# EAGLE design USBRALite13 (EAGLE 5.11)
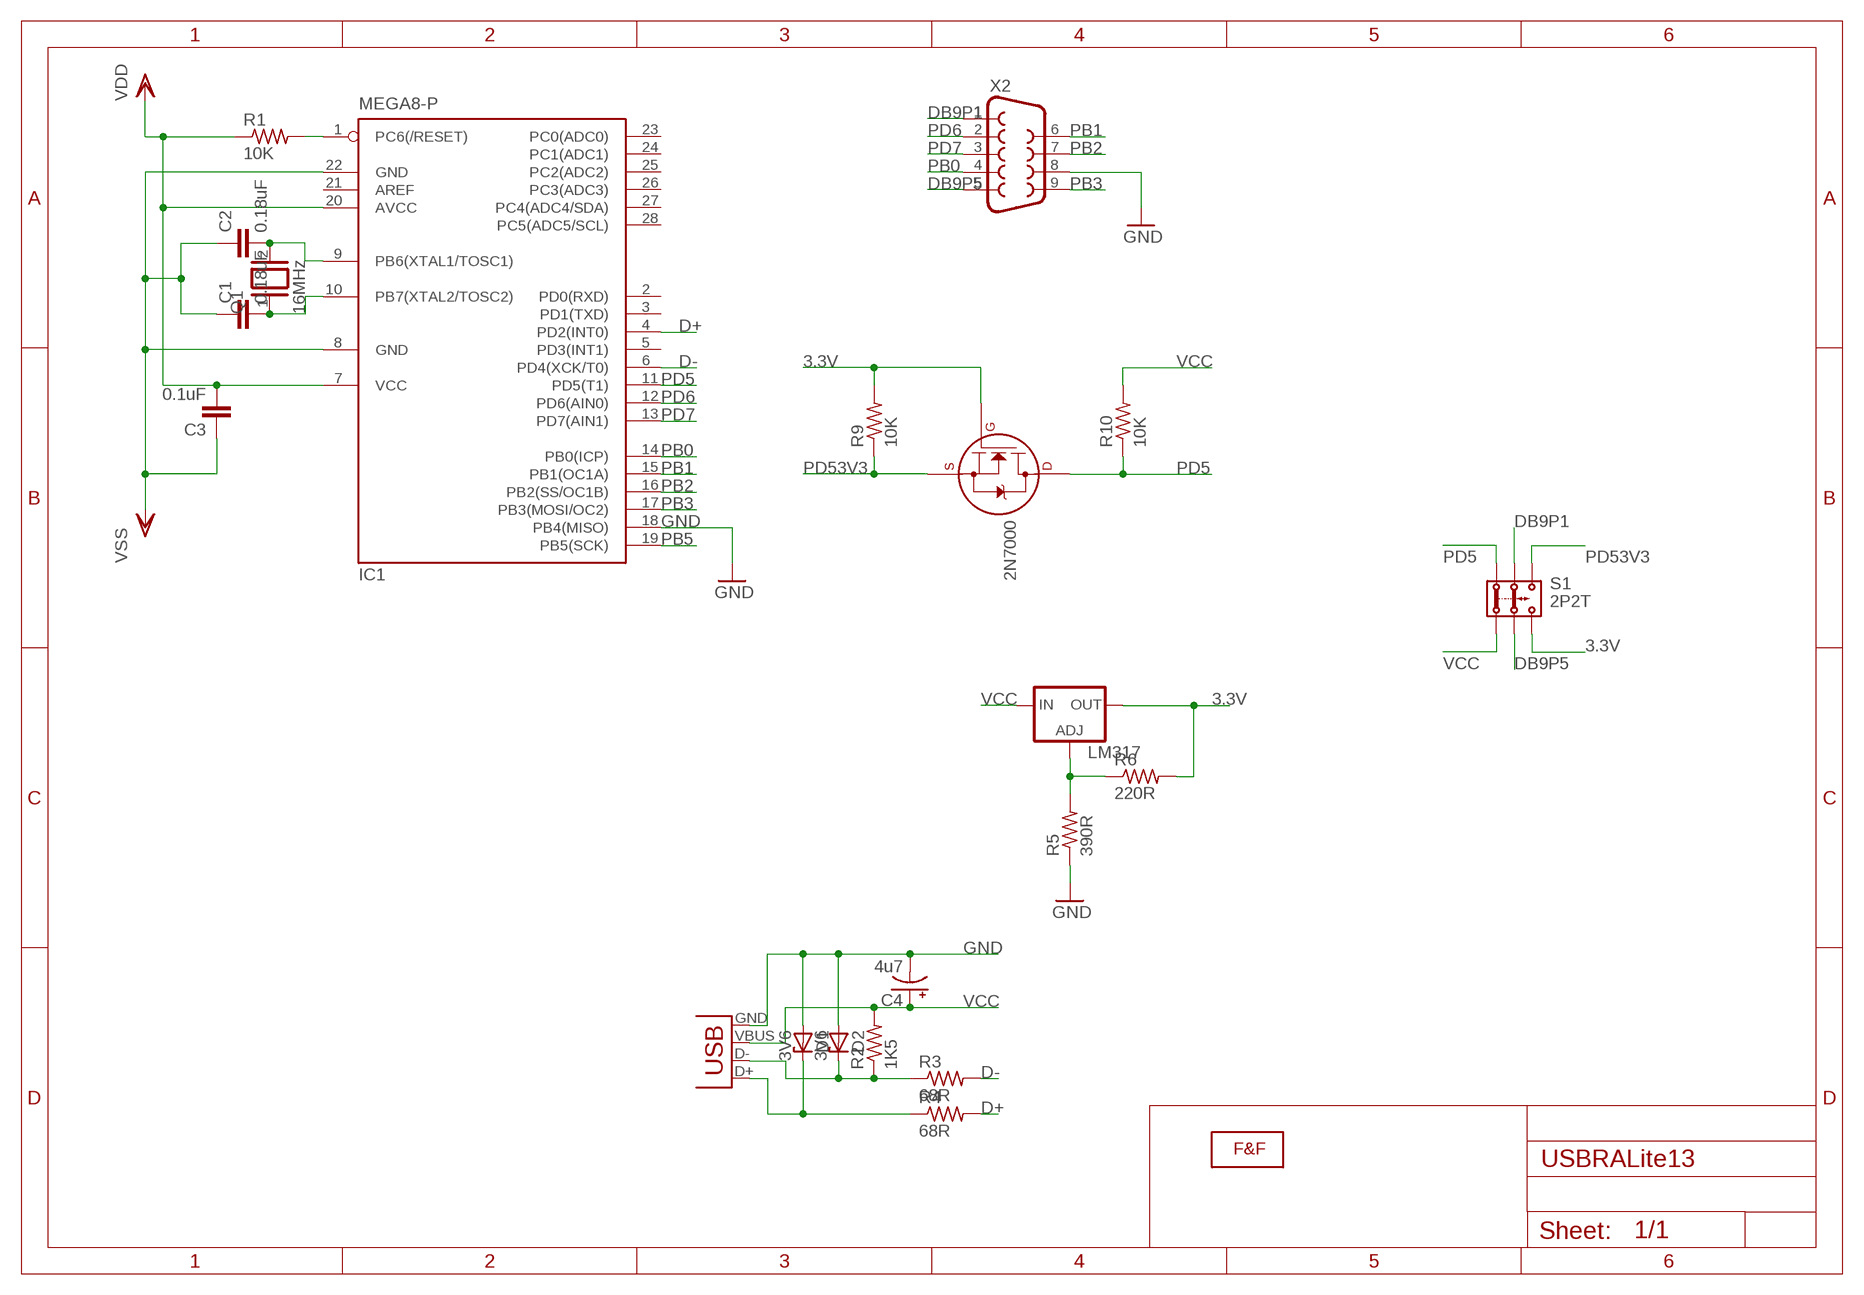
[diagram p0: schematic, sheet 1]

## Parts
2N7000  2N7000_TO92  [TO-92]
C1  0.18uF  C-EU050-024X044  [C050-024X044]
C2  0.18uF  C-EU050-024X044  [C050-024X044]
C3  0.1uF  C-EU050-024X044  [C050-024X044]
C4  4u7  CPOL-USE2.5-6  [E2,5-6]
D1  3V6  ZENER-DIODEZD-5  [ZDIO-5]
D2  3V6  ZENER-DIODEZD-5  [ZDIO-5]
IC1  MEGA8-P  [DIL28-3]
LM317  LM317TS  [317TS]
Q1  16MHz  XTAL/S  [QS]
R1  10K  R-US_0207/10  [0207/10]
R2  1K5  R-US_0207/10  [0207/10]
R3  68R  R-US_0207/10  [0207/10]
R4  68R  R-US_0207/10  [0207/10]
R5  390R  R-US_0207/10  [0207/10]
R6  220R  R-US_0207/10  [0207/10]
R9  10K  R-US_0207/10  [0207/10]
R10  10K  R-US_0207/10  [0207/10]
S1  2P2T  [2P2T]
U$1  LOGOLOGO_WITHOUT_SMOKE_SMALL  [LOGO2_SMALL]
X1  USBPTH  [USB-B-PTH]
X2  DB9MALE  [DB9_MALE]

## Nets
3.3V: 2N7000.2(G) LM317.2(OUT) R6.2 R9.2 S1.3.2
D+: IC1.4(PD2(INT0)) R4.2
D-: IC1.6(PD4(XCK/T0)) R3.2
DB9P1: S1.2.1 X2.1
DB9P5: S1.2.2 X2.5
GND: C1.1 C2.1 C3.1 C4.- D1.A D2.A IC1.8(GND) IC1.18(PB4(MISO)) IC1.22(GND) R5.1 X1.GND X2.8 ; supply symbol labelled VSS
N$1: IC1.1(PC6(/RESET)) R1.2
N$2: C2.2 IC1.9(PB6(XTAL1/TOSC1)) Q1.2
N$3: C1.2 IC1.10(PB7(XTAL2/TOSC2)) Q1.1
N$5: LM317.1(ADJ) R5.2 R6.1
N$8: D1.C R4.1 X1.D+
N$9: D2.C R2.1 R3.1 X1.D-
PB0: IC1.14(PB0(ICP)) X2.4
PB1: IC1.15(PB1(OC1A)) X2.6
PB2: IC1.16(PB2(SS/OC1B)) X2.7
PB3: IC1.17(PB3(MOSI/OC2)) X2.9
PB5: IC1.19(PB5(SCK))
PD5: 2N7000.3(D) IC1.11(PD5(T1)) R10.1 S1.1.1
PD6: IC1.12(PD6(AIN0)) X2.2
PD7: IC1.13(PD7(AIN1)) X2.3
PD53V3: 2N7000.1(S) R9.1 S1.3.1
VCC: C3.2 C4.+ IC1.7(VCC) IC1.20(AVCC) LM317.3(IN) R1.1 R2.2 R10.2 S1.1.2 X1.VBUS ; supply symbol labelled VDD
Unconnected: IC1.2(PD0(RXD)) IC1.3(PD1(TXD)) IC1.5(PD3(INT1)) IC1.21(AREF) IC1.23(PC0(ADC0)) IC1.24(PC1(ADC1)) IC1.25(PC2(ADC2)) IC1.26(PC3(ADC3)) IC1.27(PC4(ADC4/SDA)) IC1.28(PC5(ADC5/SCL))

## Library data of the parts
2N7000 = transistors:2N700*: 2N7000, 2N7002, NDS7002A N-channel enhancement mode MOSFET
C1-C3 = rcl:C-EU: CAPACITOR, European symbol
C4 = adafruit:CPOL-US: POLARIZED CAPACITOR, American symbol
D1 D2 = diode:ZENER-DIODE: Z-Diode
IC1 = atmel:MEGA8-P: MICROCONTROLLER 8 Kbytes FLASH, 1 kbytes SRAM, 512 bytes EEPROM, USART, 4-channel 10 bit ADC, 2-channel 8 bit ADC Pin compatible with Atmega48, ATMega88, ATMega168 Source: avr.lbr; OC_FARNELL: unknown; OC_NEWARK: unknown
LM317 = v-reg:LM317TS: VOLTAGE REGULATOR
Q1 = special:XTAL/S: CRYSTAL
R1-R6 R9 R10 = adafruit:R-US_: RESISTOR, American symbol
S1 = Itead_BP_110825:2P2T: BAS011
U$1 = F&F:LOGO: Faísca e Fumaça Logo
X1 = SparkFun:USB: USB Connectors USB-B-PTH is fully proven SKU : PRT-00139 USB-miniB is fully proven SKU : PRT-00587 USB-A-PCB is untested. USB-A-H is throughly reviewed, but untested. Spark Fun Electronics SKU : PRT-00437 USB-B-SMT is throughly reviewed, but untested. Needs silkscreen touching up. USB-A-S has not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
X2 = SparkFun:DB9: DB9 Connector Standard DB9 (D-Sub 9) serial connector. Can be used for CAN bus as well as RS485 and RS232. Footprint production proven. Spark Fun Electronics SKU : PRT-00429

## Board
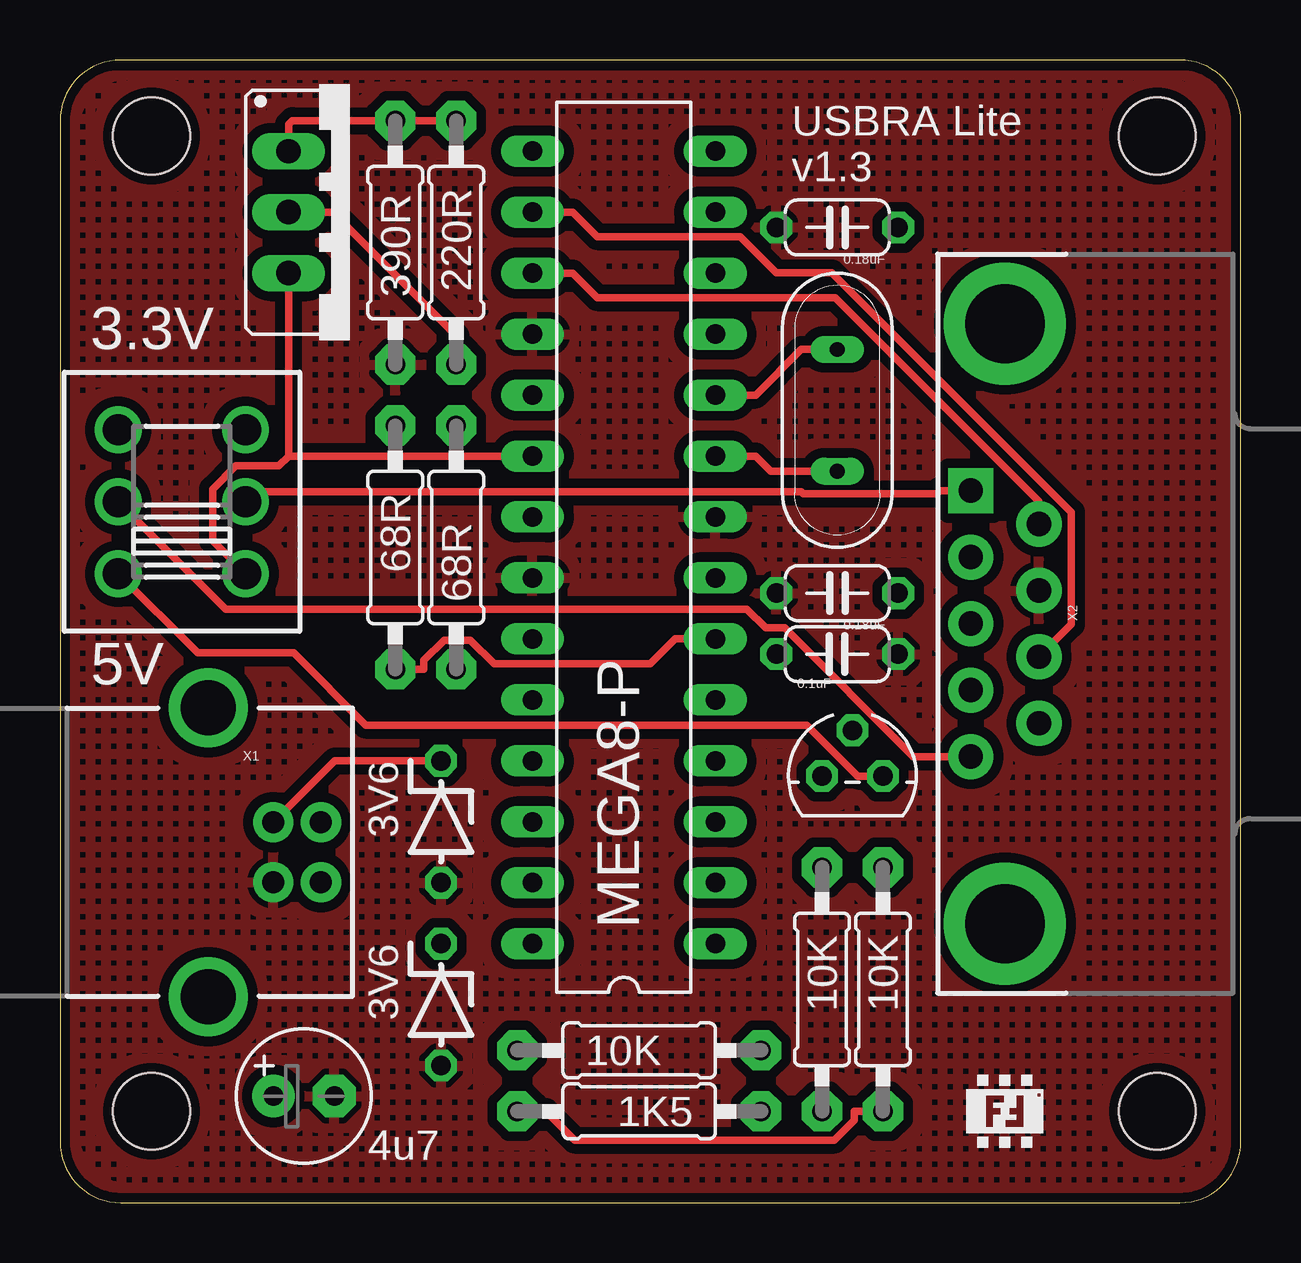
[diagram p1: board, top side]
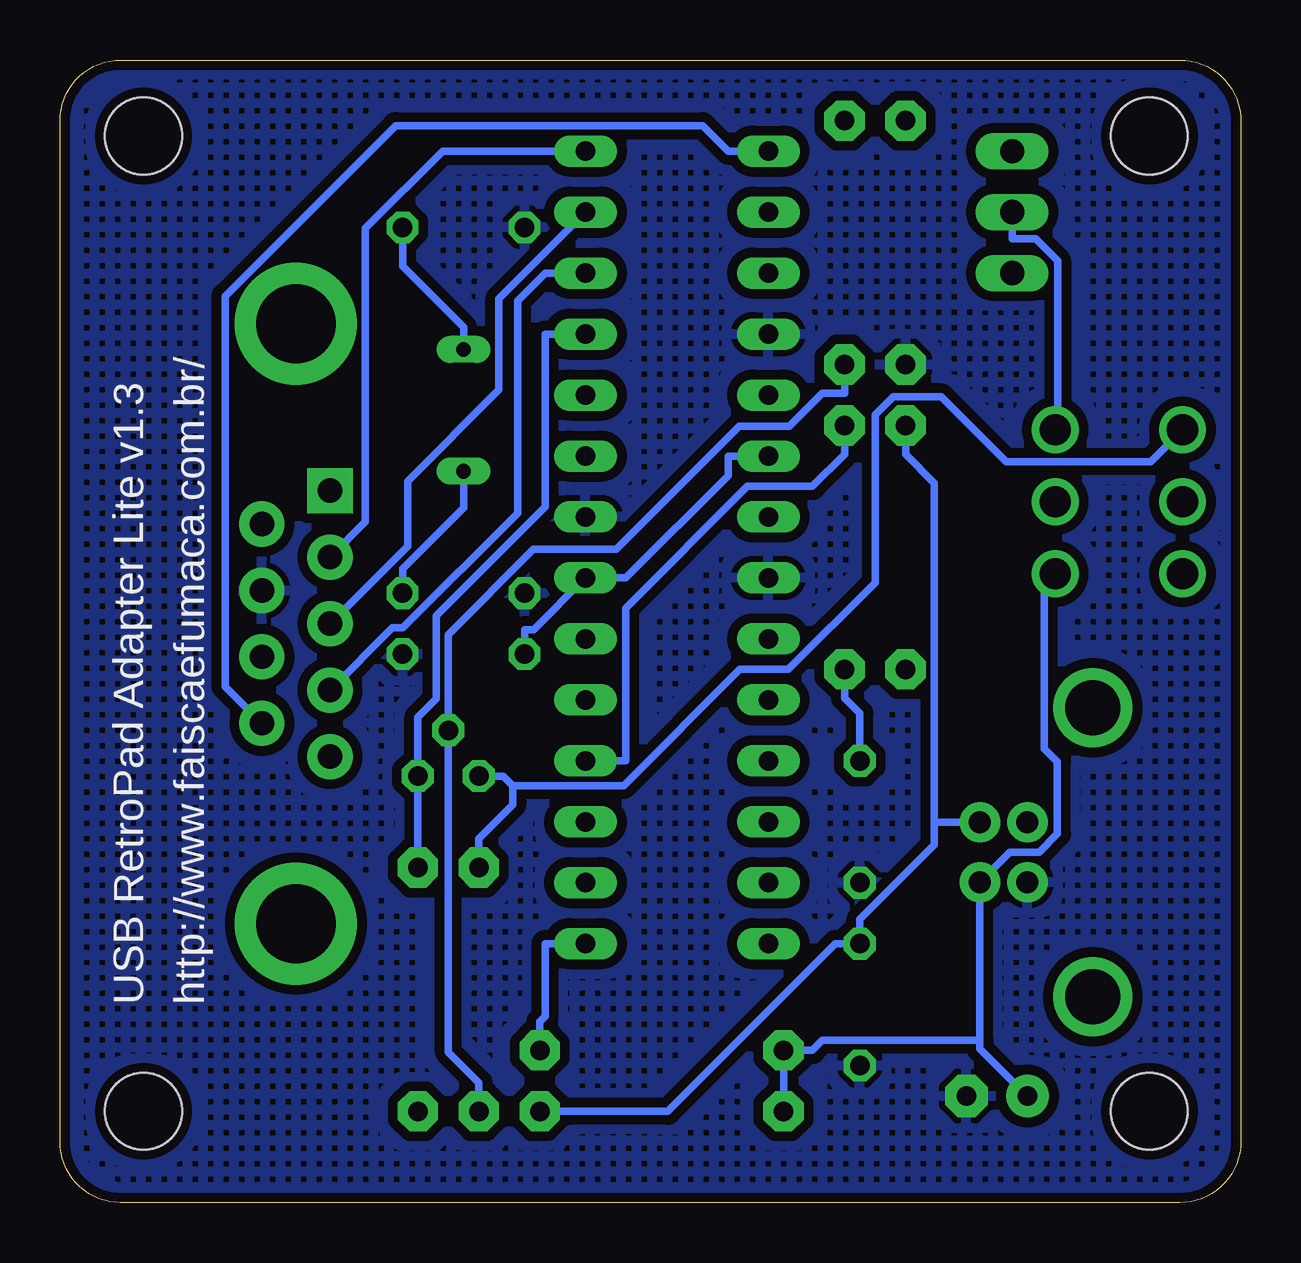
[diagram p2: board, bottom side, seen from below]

Size 49.2 x 47.62 mm. Coordinates in mm from the lower left corner, seen from the top.
Outline: 49.2,45.08 arc90 46.66,47.62 2.54,47.62 arc90 0,45.08 0,2.54 arc90 2.54,0 46.66,0 arc90 49.2,2.54 49.2,45.08
Copper layers (1*16): Top 0.035mm / dielectric 1.5mm / Bottom 0.035mm
Design rules "ITead_rule": minimum track width 6mil, minimum drill 12mil, track to track 6mil, track to pad 6mil, pad to pad 6mil, via to via 6mil, smd to smd 0mil, copper to edge 10mil, drill to drill 10mil, minimum pad ring 10mil, minimum via ring 6mil, stop-mask expansion 2mil, vias tented up to drill 100mil, thermal gap 10mil
Holes 3.2 mm at 3.81,44.45 3.81,3.81 45.72,44.45 45.72,3.81

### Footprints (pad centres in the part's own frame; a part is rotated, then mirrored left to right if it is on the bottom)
TO-92 = drill 0.813 octagon: 1 -1.27,0; 2 0,1.905; 3 1.27,0
C050-024X044 = drill 0.813 octagon: 1 -2.54,0; 2 2.54,0
E2,5-6 = drill 0.813 pad 1.778 round: + -1.27,0 | drill 0.813 pad 1.778 octagon: - 1.27,0
ZDIO-5 = drill 0.813 octagon: A 2.54,0; C -2.54,0
DIL28-3 = drill 0.813 long: 1 -16.51,-3.81; 2 -13.97,-3.81; 3 -11.43,-3.81; 4 -8.89,-3.81; 5 -6.35,-3.81; 6 -3.81,-3.81; 7 -1.27,-3.81; 8 1.27,-3.81; 9 3.81,-3.81; 10 6.35,-3.81; 11 8.89,-3.81; 12 11.43,-3.81; 13 13.97,-3.81; 14 16.51,-3.81; 15 16.51,3.81; 16 13.97,3.81; 17 11.43,3.81; 18 8.89,3.81; 19 6.35,3.81; 20 3.81,3.81; 21 1.27,3.81; 22 -1.27,3.81; 23 -3.81,3.81; 24 -6.35,3.81; 25 -8.89,3.81; 26 -11.43,3.81; 27 -13.97,3.81; 28 -16.51,3.81
317TS = drill 1.016 long: 1 -2.54,-2.54; 2 0,-2.54; 3 2.54,-2.54
QS = drill 0.61 long: 1 -2.54,0; 2 2.54,0
0207/10 = drill 0.813 pad 1.676 octagon: 1 -5.08,0; 2 5.08,0
2P2T = drill 1.3 pad 1.93 round: 1.1 -3,2.65; 1.2 -3,-2.65; 2.1 0,2.65; 2.2 0,-2.65; 3.1 3,2.65; 3.2 3,-2.65
USB-B-PTH = drill 0.914 pad 1.676 round: D+ 0,1.25; D- 1.981,1.25; GND 0,-1.25; VBUS 1.981,-1.25 | drill 2.286 round: S1 -2.718,-6.02; S2 -2.718,6.02
DB9_MALE = drill 1.016 pad 1.88 round: 1 5.54,-1.42; 2 2.77,-1.42; 3 0,-1.42; 4 -2.77,-1.42; 6 4.15,1.42; 7 1.38,1.42; 8 -1.38,1.42; 9 -4.15,1.42 | drill 1.016 pad 1.88 square: 5 -5.54,-1.42 | drill 3.302 pad 5.08 round: G1 -12.5,0; G2 12.5,0

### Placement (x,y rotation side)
2N7000  33.02,17.78 0 top
C1  32.38,40.64 0 top
C2  32.38,25.4 0 top
C3  32.38,22.86 180 top
C4  10.16,4.45 0 top
D1  15.88,15.88 270 top
D2  15.88,8.26 270 top
IC1  23.5,27.3 90 top
LM317  12.06,41.27 270 top
Q1  32.38,33.02 270 top
R1  24.13,6.35 0 top
R2  24.13,3.81 180 top
R3  13.97,27.3 270 top
R4  16.51,27.3 90 top
R5  13.97,40.01 90 top
R6  16.51,40.01 270 top
R9  31.75,8.89 270 top
R10  34.29,8.89 270 top
S1  5.08,29.21 90 top
U$1  39.37,3.81 0 top
X1  8.89,14.61 0 top
X2  39.37,24.13 270 top

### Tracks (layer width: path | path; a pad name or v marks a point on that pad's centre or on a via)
3.3V
  Top 0.305: R6.2 16.51,36.12 11.4,41.22 11.4,41.27 LM317.2
  Bottom 0.305: LM317.2 9.53,40.16 8.55,40.16 7.63,39.24 7.63,32.31 S1.3.2 | R9.2 31.75,5 33.02,6.27 2N7000.2 33.02,23.68 29.47,27.22 26.03,27.22 20.9,32.35 18.81,32.35 17.43,33.73 16.51,33.73 R6.2
D+
  Bottom 0.305: IC1.4 25.63,18.41 25.63,24.78 20.57,29.84 17.86,29.84 16.51,31.19 R4.2
D-
  Top 0.305: IC1.6 25.63,23.5 24.59,22.45 18.09,22.45 17.1,23.44 16.01,23.44 15.16,22.6 15.16,22.23 R3.2
DB9P1
  Top 0.305: X2.1 35.55,18.59 30.19,23.95 29.4,23.95 28.62,24.73 6.91,24.73 S1.2.1
DB9P5
  Top 0.305: X2.5 36.65,29.67 36.52,29.54 30.96,29.54 30.89,29.62 8.14,29.62 S1.2.2
GND
  pour Bottom (isolate 0.406, hatched): 0,46.99 49.53,46.99 49.53,0 0,0
  pour Top (isolate 0.406, hatched): 0,46.99 49.53,46.99 49.53,0 0,0
N$1
  Bottom 0.305: IC1.1 28.98,10.79 28.98,7.77 29.21,7.54 R1.2
N$2
  Top 0.305: IC1.9 28.98,31.11 29.62,30.48 Q1.2
  Bottom 0.305: C2.2 34.92,26.42 32.38,28.96 Q1.2
N$3
  Top 0.305: IC1.10 28.98,33.66 30.89,35.56 Q1.1
  Bottom 0.305: Q1.1 32.38,36.47 34.92,39.01 C1.2
N$5
  Top 0.305: LM317.1 9.53,44.93 9.68,45.09 R5.2 R6.1
N$8
  Top 0.305: X1.D+ 11.45,18.41 D1.C
  Bottom 0.305: R4.1 16.51,21.03 15.88,20.4 D1.C
N$9
  Bottom 0.305: 12.76,15.86 12.76,29.98 13.97,31.19 R3.1 | 12.76,15.86 12.76,14.92 15.88,11.81 D2.C 16.89,10.79 23.88,3.81 28.02,3.81 R2.1 | 12.76,15.86 X1.D-
PB0
  Bottom 0.305: IC1.14 33.26,43.81 36.47,40.6 36.47,28.38 X2.4
PB1
  Bottom 0.305: IC1.15 21.36,43.81 22.43,44.88 35.22,44.88 42.32,37.78 42.32,21.51 X2.6
PB2
  Top 0.305: IC1.16 21.36,41.27 22.38,40.26 28.33,40.26 29.85,38.75 32.16,38.75 42.14,28.77 42.14,24.1 X2.7
PB3
  Top 0.305: IC1.17 21.36,38.73 22.38,37.72 32.3,37.72 40.79,29.23 X2.9
PD5
  Top 0.305: S1.1.1 5.73,22.91 9.73,22.91 12.73,19.91 31.12,19.91 33.25,17.78 2N7000.3
  Bottom 0.305: IC1.11 28.98,36.2 28.98,29 33.53,24.46 33.53,20.99 34.29,20.23 2N7000.3 R10.1
PD6
  Bottom 0.305: IC1.12 28.98,38.73 30.13,37.59 30.13,28.73 34.91,23.95 35.36,23.95 X2.2
PD7
  Bottom 0.305: X2.3 34.72,27.36 34.72,30.06 30.91,33.87 30.91,37.67 IC1.13
PD53V3
  Bottom 0.305: R9.1 31.75,15.16 30.34,16.58 30.34,17.38 | 30.34,17.38 30.73,17.78 2N7000.1 | S1.3.1 3.76,30.88 9.78,30.88 12.48,33.58 14.49,33.58 15.24,32.83 15.24,25.83 18.85,22.23 20.88,22.23 25.72,17.38 30.34,17.38
VCC
  Top 0.305: 9.53,31.11 9.53,37.62 LM317.3 | S1.1.2 6.36,27.59 6.36,29.73 7.33,30.71 9.12,30.71 9.53,31.11 | 9.53,31.11 18.01,31.11 IC1.20 | R10.2 33.1,3.81 33.1,3.44 32.27,2.61 21.45,2.61 20.24,3.81 R2.2
  Bottom 0.305: 10.87,6.77 10.87,6.43 C4.+ | 10.87,6.77 X1.VBUS 9.62,14.61 8.4,14.61 7.64,15.37 7.64,18.37 8.18,18.91 8.18,25.76 S1.1.2 | 10.87,6.77 17.44,6.77 17.86,6.35 R1.1 R2.2 | IC1.20 21.36,31.11 21.36,30.3 25.63,26.04 IC1.7 29.46,23.88 29.84,23.88 C3.2

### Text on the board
tPlace: USBRA Lite | v1.3 | 3.3V | 5V
bPlace: http://www.faiscaefumaca.com.br/ | USB RetroPad Adapter Lite v1.3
